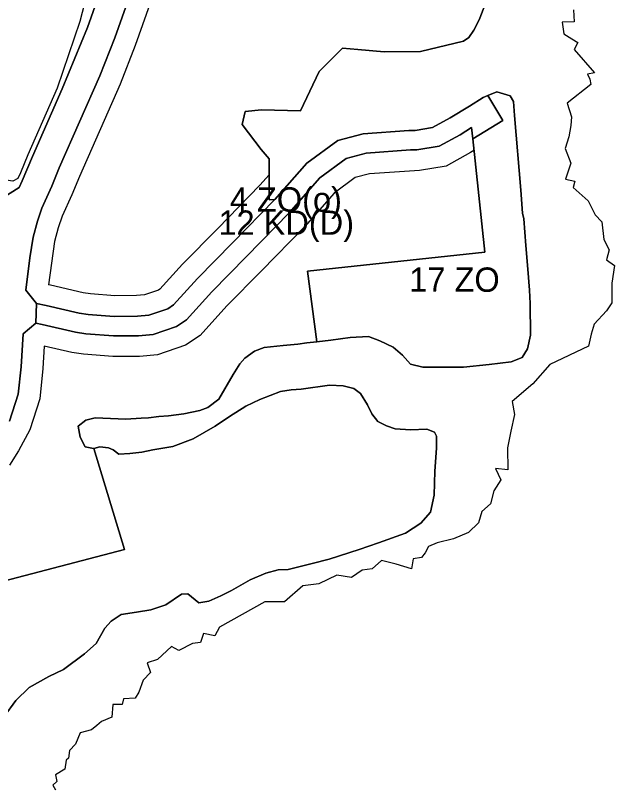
# Model space of a CAD drawing. Extents: x 7418056 to 7420315, y 5537846 to 5539505.
# Drawn here: x 7419814.6 to 7420060.7, y 5538250.2 to 5538568.2 of the extents above; entities that cross this region are included whole.
import ezdxf

# ---------------------------------------------------------------- set-up
doc = ezdxf.new("R2010")
doc.units = 0
for name, color, linetype in [('linie_rozgraniczajace', 7, 'Continuous'), ('linie_zabudowy_nieprzekraczalne', 7, 'Continuous'), ('oznaczenia_przeznaczen', 7, 'Continuous')]:
    doc.layers.add(name, color=color, linetype=linetype)

msp = doc.modelspace()

# ---------------------------------------------------------------- linework, layer by layer
at = {"layer": 'linie_rozgraniczajace'}
for points in [[(7419813.18, 5538712.6), (7419870.81, 5538716.16), (7419867.11, 5538696.85), (7419864.44, 5538670.2), (7419863.12, 5538653.88), (7419863.07, 5538653.49), (7419861, 5538628.16), (7419860.06, 5538617.95), (7419857.98, 5538606.25), (7419853.62, 5538590.02), (7419853.34, 5538589.23), (7419844.15, 5538563.23), (7419833.74, 5538537.98), (7419821.56, 5538510.24), (7419817.34, 5538500.18), (7419816.12, 5538497.47), (7419809.77, 5538493.53)], [(7419809.77, 5538493.53), (7419816.12, 5538497.47), (7419817.34, 5538500.18), (7419821.56, 5538510.24), (7419833.74, 5538537.98), (7419844.15, 5538563.23), (7419853.34, 5538589.23)], [(7419865.09, 5538586.45), (7419855.39, 5538559.04), (7419849.23, 5538543.42), (7419832.6, 5538505.52), (7419829.53, 5538497.98), (7419825.46, 5538489.06), (7419823.57, 5538483.6), (7419821.81, 5538477.08), (7419820.48, 5538468.58), (7419818.78, 5538455.3), (7419823.2, 5538449.8), (7419822.94, 5538441.71), (7419817.71, 5538437.34), (7419816.88, 5538423.89), (7419815.67, 5538412.56), (7419812.13, 5538401.51)], [(7420007.47, 5538572.46), (7420005.33, 5538567.06), (7420004.35, 5538564.69), (7420002.85, 5538562.14), (7420000.88, 5538559.16), (7419998.71, 5538557.61), (7419981.02, 5538553.32), (7419966.05, 5538553.26), (7419955.28, 5538554.13), (7419948.97, 5538554.79), (7419939.38, 5538545.16), (7419931.72, 5538528.96), (7419915.61, 5538529.42), (7419908.98, 5538528.78), (7419907.72, 5538523.37), (7419915.53, 5538513.15), (7419918.84, 5538509.22), (7419918.78, 5538492.41), (7419921.18, 5538492.5), (7419903.81, 5538474.72), (7419889.4, 5538460.18), (7419879.56, 5538449.28), (7419877.13, 5538447.66), (7419869.41, 5538445.03), (7419864.73, 5538444.6), (7419855.11, 5538444.54), (7419844.45, 5538445.37), (7419840.8, 5538445.93), (7419827.22, 5538449.06), (7419823.2, 5538449.8), (7419818.78, 5538455.3), (7419820.48, 5538468.58), (7419821.81, 5538477.08), (7419823.57, 5538483.6), (7419825.46, 5538489.06), (7419829.53, 5538497.98), (7419832.6, 5538505.52), (7419849.23, 5538543.42), (7419855.39, 5538559.04), (7419865.09, 5538586.45)], [(7420043.81, 5538570.47), (7420044.19, 5538565.56), (7420039.26, 5538565.45), (7420039.96, 5538560.63), (7420043.13, 5538558.56), (7420045.67, 5538557.04), (7420044.18, 5538554.22), (7420052.56, 5538544.6), (7420049.6, 5538544.08), (7420050.57, 5538542.02), (7420051.03, 5538539.76), (7420041.24, 5538532.1), (7420043.11, 5538526.5), (7420042.82, 5538522.96), (7420041.88, 5538518.3), (7420040.46, 5538513.54), (7420042.74, 5538507.52), (7420040.61, 5538500.9), (7420044.42, 5538500.13), (7420043.78, 5538497.44), (7420049.93, 5538492.07), (7420052.7, 5538486.32), (7420055.57, 5538483.4), (7420056.39, 5538476.07), (7420058.52, 5538471.9), (7420057.48, 5538467.79), (7420060.72, 5538465.47), (7420059.68, 5538458.18), (7420059.64, 5538450.06), (7420057.47, 5538446.85), (7420052.3, 5538441.38), (7420051.09, 5538437.3), (7420050.06, 5538432.31), (7420034.18, 5538424.76), (7420027.17, 5538416.89), (7420018.71, 5538409.66), (7420019.59, 5538404.29), (7420018.14, 5538397.45), (7420016.68, 5538390.62), (7420016.91, 5538381.58), (7420011.85, 5538382.07), (7420014, 5538377.35), (7420011.13, 5538372.96), (7420009.74, 5538367.59), (7420006.15, 5538364.36), (7420004.82, 5538359.75), (7420000.68, 5538355.78), (7419994.57, 5538353.21), (7419987.82, 5538351.49), (7419984.23, 5538350.05), (7419982.93, 5538347.37), (7419981.45, 5538345.56), (7419977.93, 5538344.96), (7419977.29, 5538340.85), (7419971.03, 5538342.76), (7419965.02, 5538344.33), (7419961.18, 5538340.9), (7419957.05, 5538340.35), (7419952.7, 5538337.28), (7419946.57, 5538338.28), (7419939.26, 5538334.68), (7419932.6, 5538333.91), (7419925.06, 5538327.34), (7419916.97, 5538327.26), (7419898.4, 5538316.91), (7419896.53, 5538313.33), (7419891.87, 5538314.26), (7419890.65, 5538310.6), (7419887.36, 5538310.18), (7419881.74, 5538307.25), (7419878.73, 5538308.94), (7419872.91, 5538303.68), (7419868.65, 5538302.24), (7419870.01, 5538298.28), (7419866.98, 5538295.13), (7419865.28, 5538290.18), (7419863.74, 5538287.68), (7419858.92, 5538287.51), (7419858.43, 5538285.18), (7419854.61, 5538285.15), (7419854.19, 5538279.97), (7419849.88, 5538278.17), (7419848.04, 5538276.49), (7419845.8, 5538274.73), (7419841.12, 5538273.5), (7419839.25, 5538268.81), (7419836.82, 5538266.27), (7419836.3, 5538263.03), (7419835.36, 5538262.27), (7419834.91, 5538258.58), (7419831.07, 5538256.29), (7419831.57, 5538253.44), (7419829.98, 5538251.95), (7419831.05, 5538250.03)], [(7419915.53, 5538513.15), (7419907.72, 5538523.37), (7419908.98, 5538528.78), (7419915.61, 5538529.42), (7419931.72, 5538528.96), (7419939.38, 5538545.16), (7419948.97, 5538554.79), (7419955.28, 5538554.13), (7419966.05, 5538553.26), (7419981.02, 5538553.32), (7419998.71, 5538557.61), (7420000.88, 5538559.16), (7420002.85, 5538562.14), (7420004.35, 5538564.69), (7420005.33, 5538567.06), (7420007.47, 5538572.46)], [(7419963.75, 5538351.6), (7419974.79, 5538355.48), (7419981.07, 5538359.61), (7419985.05, 5538364.08), (7419986.63, 5538371.16), (7419986.94, 5538380.92), (7419987.57, 5538390.4), (7419987.51, 5538395.41), (7419986.7, 5538397.02), (7419983.64, 5538398.18), (7419976.92, 5538397.91), (7419970.58, 5538398.38), (7419967.09, 5538399.66), (7419963.44, 5538401.38), (7419961.01, 5538404.57), (7419959.28, 5538408.23), (7419956.37, 5538412.84), (7419953.56, 5538414.88), (7419949.22, 5538415.99), (7419943.55, 5538416.31), (7419931.92, 5538414.72), (7419927.91, 5538414.41), (7419923.5, 5538413.66), (7419915.02, 5538410.45), (7419909.26, 5538407.63), (7419902.48, 5538403.47), (7419896.62, 5538399.5), (7419887.65, 5538394.27), (7419879.18, 5538391.05), (7419871.06, 5538389.72), (7419866.5, 5538388.82), (7419861.51, 5538388.18), (7419857.08, 5538388), (7419854.7, 5538389.77), (7419852.81, 5538390.55), (7419849.21, 5538390.99), (7419846.75, 5538390.34), (7419846.65, 5538390.3), (7419843.18, 5538391.02), (7419841.16, 5538394.95), (7419840.4, 5538399.5), (7419843.46, 5538401.93), (7419847.28, 5538402.95), (7419859.87, 5538402.39), (7419866.24, 5538402.8), (7419869.2, 5538402.92), (7419873.48, 5538403.39), (7419877.47, 5538403.69), (7419883.81, 5538404.55), (7419890.29, 5538405.84), (7419893.59, 5538407.12), (7419898.1, 5538410.61), (7419903.96, 5538420.67), (7419906.79, 5538425.08), (7419908.85, 5538427.45), (7419912.74, 5538430.33), (7419916.7, 5538431.79), (7419924.56, 5538432.53), (7419930.55, 5538433.21), (7419934.26, 5538433.65), (7419938.39, 5538434.12), (7419944.12, 5538434.76), (7419952.09, 5538435.94), (7419959.69, 5538436.25), (7419964.34, 5538434.58), (7419969.76, 5538431.94), (7419973.62, 5538428.65), (7419976.93, 5538424.91), (7419981.96, 5538423.69), (7419998.6, 5538423.65), (7420009.17, 5538424.79), (7420018.3, 5538425.88), (7420022.82, 5538427.64), (7420024.97, 5538431.17), (7420026.18, 5538436.81), (7420026.08, 5538449.85), (7420025.8, 5538455.34), (7420025.07, 5538463.94), (7420024.28, 5538473.7), (7420023.43, 5538484.65), (7420022.95, 5538486.98), (7420022.18, 5538496.35), (7420019.58, 5538527.08), (7420019.27, 5538532.89), (7420017.79, 5538535.09), (7420012.38, 5538536.86), (7420008.61, 5538535.27), (7420006.72, 5538534.48), (7420001.08, 5538530.9), (7419993.22, 5538526.1), (7419985.98, 5538522.12), (7419978.82, 5538520.89), (7419976.27, 5538520.9), (7419957.43, 5538519.48), (7419947, 5538516.83), (7419934.25, 5538507.45), (7419921.18, 5538492.5), (7419918.78, 5538492.41), (7419918.84, 5538509.22), (7419915.53, 5538513.15)], [(7419812.13, 5538401.51), (7419815.67, 5538412.56), (7419816.88, 5538423.89), (7419817.71, 5538437.34), (7419822.94, 5538441.71), (7419825.6, 5538441.23), (7419839.3, 5538438.06), (7419843.54, 5538437.42), (7419854.82, 5538436.54), (7419865.11, 5538436.6), (7419871.09, 5538437.15), (7419880.71, 5538440.43), (7419884.83, 5538443.18), (7419895.21, 5538454.68), (7419909.52, 5538469.1), (7419927.1, 5538487.13), (7419939.7, 5538501.52), (7419950.48, 5538509.47), (7419958.72, 5538511.55), (7419976.87, 5538512.92), (7419979.49, 5538512.9), (7419988.66, 5538514.45), (7419997.23, 5538519.18), (7420001.99, 5538522.08), (7420002.47, 5538517.52), (7420007.37, 5538470.88), (7419934.56, 5538463.11), (7419938.39, 5538434.12), (7419934.26, 5538433.65), (7419930.55, 5538433.21), (7419924.56, 5538432.53), (7419916.7, 5538431.79), (7419912.74, 5538430.33), (7419908.85, 5538427.45), (7419906.79, 5538425.08), (7419903.96, 5538420.67), (7419898.1, 5538410.61), (7419893.59, 5538407.12), (7419890.29, 5538405.84), (7419883.81, 5538404.55), (7419877.47, 5538403.69), (7419873.48, 5538403.39), (7419869.2, 5538402.92), (7419866.24, 5538402.8), (7419859.87, 5538402.39), (7419847.28, 5538402.95), (7419843.46, 5538401.93), (7419840.4, 5538399.5), (7419841.16, 5538394.95), (7419843.18, 5538391.02), (7419846.65, 5538390.3), (7419846.75, 5538390.34), (7419859.4, 5538348.83), (7419809.68, 5538335.84)], [(7419809.68, 5538335.84), (7419859.4, 5538348.83), (7419846.75, 5538390.34), (7419849.21, 5538390.99), (7419852.81, 5538390.55), (7419854.7, 5538389.77), (7419857.08, 5538388), (7419861.51, 5538388.18), (7419866.5, 5538388.82), (7419871.06, 5538389.72), (7419879.18, 5538391.05), (7419887.65, 5538394.27), (7419896.62, 5538399.5), (7419902.48, 5538403.47), (7419909.26, 5538407.63), (7419915.02, 5538410.45), (7419923.5, 5538413.66), (7419927.91, 5538414.41), (7419931.92, 5538414.72), (7419943.55, 5538416.31), (7419949.22, 5538415.99), (7419953.56, 5538414.88), (7419956.37, 5538412.84), (7419959.28, 5538408.23), (7419961.01, 5538404.57), (7419963.44, 5538401.38), (7419967.09, 5538399.66), (7419970.58, 5538398.38), (7419976.92, 5538397.91), (7419983.64, 5538398.18), (7419986.7, 5538397.02), (7419987.51, 5538395.41), (7419987.57, 5538390.4), (7419986.94, 5538380.92), (7419986.63, 5538371.16), (7419985.05, 5538364.08), (7419981.07, 5538359.61), (7419974.79, 5538355.48), (7419963.75, 5538351.6), (7419955.83, 5538348.84), (7419943.42, 5538344.86), (7419936.47, 5538343), (7419926.67, 5538340.6), (7419922.52, 5538340.43), (7419917.41, 5538339.07), (7419911.07, 5538336.38), (7419903.36, 5538331.92), (7419899, 5538329.73), (7419894.08, 5538327.53), (7419889.94, 5538326.93), (7419885.35, 5538330.6), (7419882.77, 5538330.5), (7419876.35, 5538326.09), (7419870.26, 5538323.98), (7419864.28, 5538323.01), (7419857.95, 5538322.11), (7419853.91, 5538319.36), (7419851.29, 5538316.53), (7419847.67, 5538310.23), (7419842.98, 5538305.88), (7419834.35, 5538299.51), (7419828.3, 5538296.68), (7419820.16, 5538292.06), (7419814.78, 5538286.82), (7419809.89, 5538280.17)], [(7419809.89, 5538280.17), (7419814.78, 5538286.82), (7419820.16, 5538292.06), (7419828.3, 5538296.68), (7419834.35, 5538299.51), (7419842.98, 5538305.88), (7419847.67, 5538310.23), (7419851.29, 5538316.53), (7419853.91, 5538319.36), (7419857.95, 5538322.11), (7419864.28, 5538323.01), (7419870.26, 5538323.98), (7419876.35, 5538326.09), (7419882.77, 5538330.5), (7419885.35, 5538330.6), (7419889.94, 5538326.93), (7419894.08, 5538327.53), (7419899, 5538329.73), (7419903.36, 5538331.92), (7419911.07, 5538336.38), (7419917.41, 5538339.07), (7419922.52, 5538340.43), (7419926.67, 5538340.6), (7419936.47, 5538343), (7419943.42, 5538344.86), (7419955.83, 5538348.84), (7419963.75, 5538351.6)]]:
    msp.add_lwpolyline(points, dxfattribs=at)
for points in [[(7419822.94, 5538441.71), (7419823.2, 5538449.8), (7419827.22, 5538449.06), (7419840.8, 5538445.93), (7419844.45, 5538445.37), (7419855.11, 5538444.54), (7419864.73, 5538444.6), (7419869.41, 5538445.03), (7419877.13, 5538447.66), (7419879.56, 5538449.28), (7419889.4, 5538460.18), (7419903.81, 5538474.72), (7419921.18, 5538492.5), (7419934.25, 5538507.45), (7419947, 5538516.83), (7419957.43, 5538519.48), (7419976.27, 5538520.9), (7419978.82, 5538520.89), (7419985.98, 5538522.12), (7419993.22, 5538526.1), (7420001.08, 5538530.9), (7420006.72, 5538534.48), (7420008.61, 5538535.27), (7420014.84, 5538525.06), (7420002.47, 5538517.52), (7420001.99, 5538522.08), (7419997.23, 5538519.18), (7419988.66, 5538514.45), (7419979.49, 5538512.9), (7419976.87, 5538512.92), (7419958.72, 5538511.55), (7419950.48, 5538509.47), (7419939.7, 5538501.52), (7419927.1, 5538487.13), (7419909.52, 5538469.1), (7419895.21, 5538454.68), (7419884.83, 5538443.18), (7419880.71, 5538440.43), (7419871.09, 5538437.15), (7419865.11, 5538436.6), (7419854.82, 5538436.54), (7419843.54, 5538437.42), (7419839.3, 5538438.06), (7419825.6, 5538441.23)], [(7419934.56, 5538463.11), (7420007.37, 5538470.88), (7420002.47, 5538517.52), (7420014.84, 5538525.06), (7420008.61, 5538535.27), (7420012.38, 5538536.86), (7420017.79, 5538535.09), (7420019.27, 5538532.89), (7420019.58, 5538527.08), (7420022.18, 5538496.35), (7420022.95, 5538486.98), (7420023.43, 5538484.65), (7420024.28, 5538473.7), (7420025.07, 5538463.94), (7420025.8, 5538455.34), (7420026.08, 5538449.85), (7420026.18, 5538436.81), (7420024.97, 5538431.17), (7420022.82, 5538427.64), (7420018.3, 5538425.88), (7420009.17, 5538424.79), (7419998.6, 5538423.65), (7419981.96, 5538423.69), (7419976.93, 5538424.91), (7419973.62, 5538428.65), (7419969.76, 5538431.94), (7419964.34, 5538434.58), (7419959.69, 5538436.25), (7419952.09, 5538435.94), (7419944.12, 5538434.76), (7419938.39, 5538434.12)]]:
    msp.add_lwpolyline(points, close=True, dxfattribs=at)
at = {"layer": 'linie_zabudowy_nieprzekraczalne'}
for points in [[(7419888.47, 5538696.71), (7419887.92, 5538693.83), (7419885.36, 5538668.31), (7419884.06, 5538652.19), (7419881.92, 5538626.35), (7419880.89, 5538615.16), (7419878.48, 5538601.52), (7419873.68, 5538583.78), (7419863.82, 5538555.89), (7419857.54, 5538539.96), (7419840.89, 5538502.02), (7419837.8, 5538494.43), (7419833.83, 5538485.72), (7419832.18, 5538480.95), (7419830.66, 5538475.33), (7419828.18, 5538457.53)], [(7419845.31, 5538593.55), (7419848.17, 5538593.31), (7419841.03, 5538565.71), (7419831.72, 5538538.31), (7419819.7, 5538510.97), (7419816.67, 5538503.53), (7419815.59, 5538501.16), (7419813.55, 5538500.05), (7419801.39, 5538501.82), (7419776.06, 5538503.53), (7419727.84, 5538507.63), (7419679.48, 5538515.57), (7419676.31, 5538521.13)], [(7420002.98, 5538512.73), (7420001.5, 5538511.83), (7419991.5, 5538506.32), (7419980.62, 5538504.47), (7419960.04, 5538503.12), (7419954.18, 5538501.64), (7419945.49, 5538495.23), (7419933.42, 5538481.44), (7419915.58, 5538463.15), (7419901.39, 5538448.84), (7419890.43, 5538436.71), (7419884.5, 5538432.75), (7419872.88, 5538428.78), (7419865.53, 5538428.11), (7419854.52, 5538428.04), (7419842.57, 5538428.98), (7419837.71, 5538429.71), (7419826.42, 5538432.32)], [(7419918.81, 5538502.71), (7419915.05, 5538498.41), (7419897.75, 5538480.67), (7419883.23, 5538466.03), (7419873.95, 5538455.77), (7419873.33, 5538455.35), (7419867.62, 5538453.4), (7419864.31, 5538453.1), (7419855.42, 5538453.04), (7419845.42, 5538453.83), (7419842.4, 5538454.29), (7419828.93, 5538457.39), (7419828.18, 5538457.53)], [(7419826.42, 5538432.32), (7419825.85, 5538423.14), (7419824.52, 5538410.7), (7419820.46, 5538398.01), (7419815.89, 5538389.39), (7419812.14, 5538383.49)]]:
    msp.add_lwpolyline(points, dxfattribs=at)

# ---------------------------------------------------------------- texts
at = {"layer": 'oznaczenia_przeznaczen'}
for s, p in [('4 ZO(o)', (7419902.64, 5538487.58)), ('12 KD(D)', (7419897.96, 5538478.06)), ('17 ZO', (7419976.38, 5538454.65))]:
    msp.add_text(s, height=10, dxfattribs=at).set_placement(p)

doc.saveas('drawing.dxf')
